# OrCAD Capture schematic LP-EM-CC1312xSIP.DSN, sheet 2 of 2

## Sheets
2 2_Mech: size A3
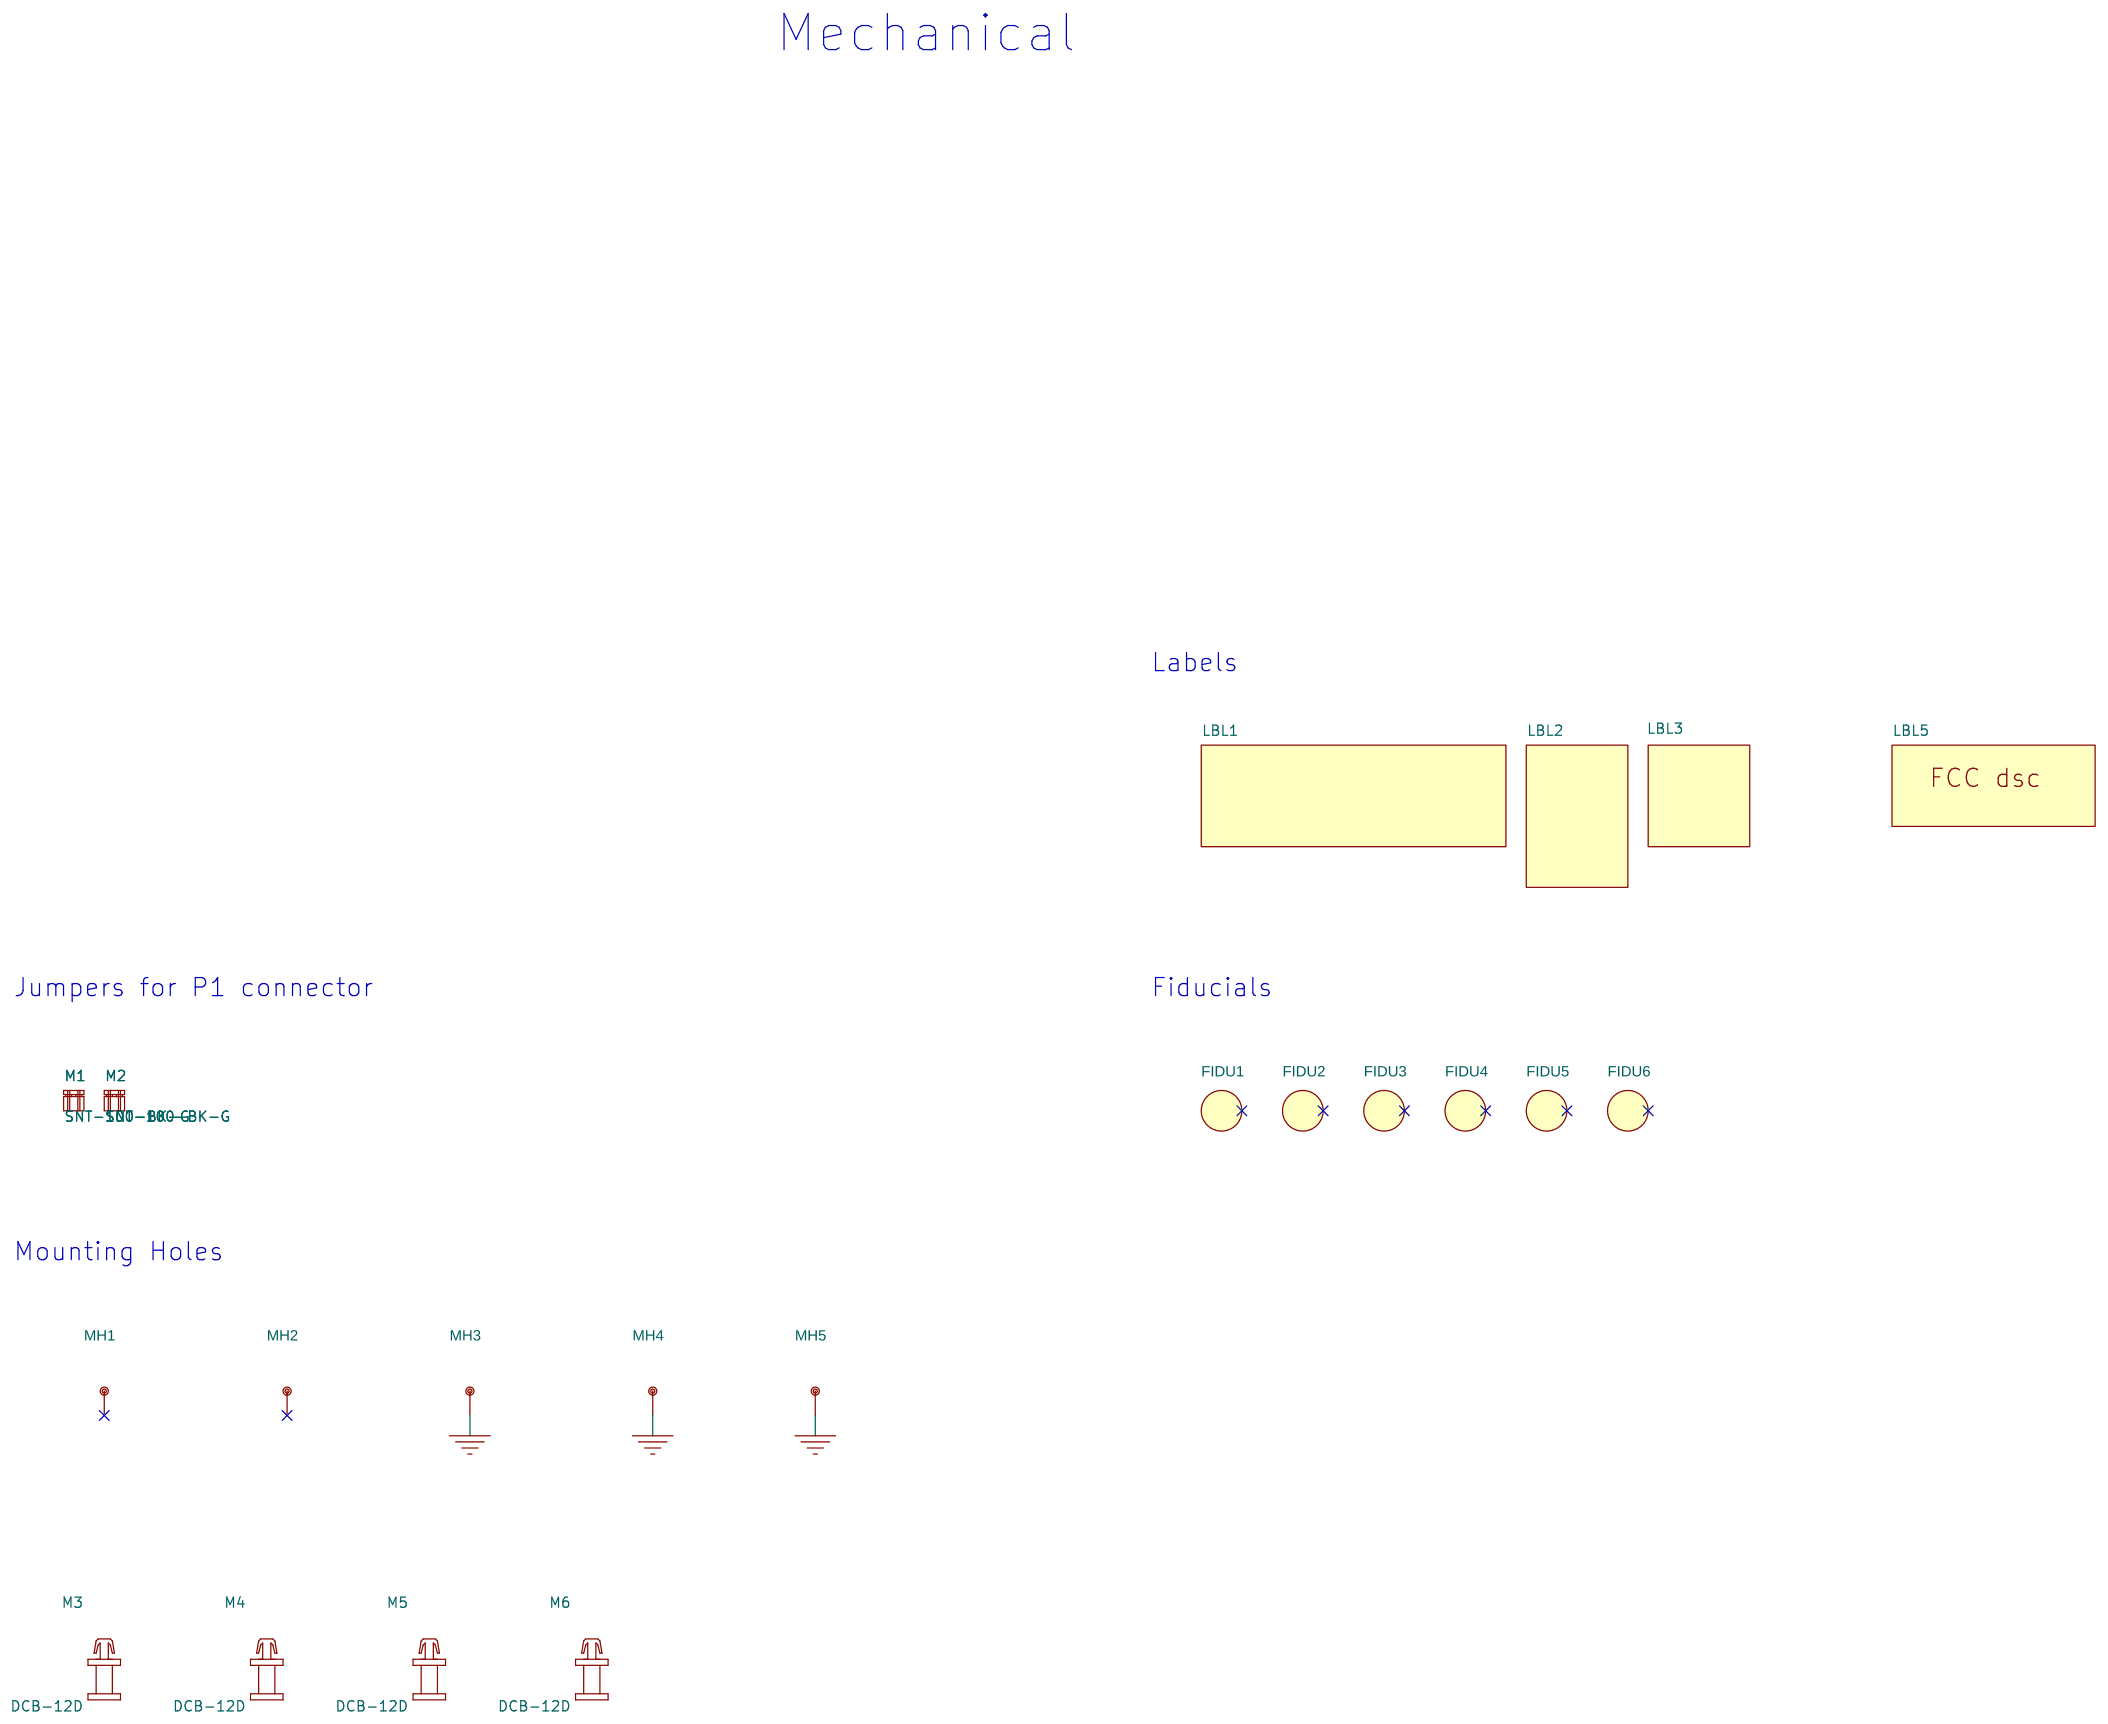
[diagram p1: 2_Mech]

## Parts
FIDU1  FIDU_1.27mm  [FID127X142]
FIDU2  FIDU_1.27mm  [FID127X142]
FIDU3  FIDU_1.27mm  [FID127X142]
FIDU4  FIDU_1.27mm  [FID127X142]
FIDU5  FIDU_1.27mm  [FID127X142]
FIDU6  FIDU_1.27mm  [FID127X142]
LBL1  TI_LOGO  [TI_LOGO_1]
LBL2  TRASH_7mm  [TRASH_7MM]
LBL3  ESD_LABEL_5x5mm  [ESD_LABEL_5X5]
LBL5  LABEL_FOR_EVALUATION_ONLY  [LABEL_FOR_EVALUATION_ONLY]
M1  SNT-100-BK-G  [SAMTEC_SNT100BKG]
M2  SNT-100-BK-G  [SAMTEC_SNT100BKG]
M3  DCB-12D  [MECH_DCB12D_A2B]
M4  DCB-12D  [MECH_DCB12D_A2B]
M5  DCB-12D  [MECH_DCB12D_A2B]
M6  DCB-12D  [MECH_DCB12D_A2B]
MH1  HOLE_3.2mm_PAD_3.8mm_PTH  [MTG320_380]
MH2  HOLE_3.2mm_PAD_3.8mm_PTH  [MTG320_380]
MH3  HOLE_3.2mm_PAD_3.8mm_PTH  [MTG320_380]
MH4  HOLE_3.2mm_PAD_3.8mm_PTH  [MTG320_380]
MH5  HOLE_1.1mm_PTH  [MTG110_170]

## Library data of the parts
FIDU1-FIDU6 = FIDMARK: NON COMPONENT, FIDUCIAL MARK, ROUND 1.27MM, SMD; Additional Datasheet URL: N/A; CLASS: IO; Country of Origin: Missing Info; Datasheet URL: N/A; Mass: N/A; Mounting Type: SMD; NOTEfied URL: https://notefied-dynamic-precision.com/NOTEfiedWebInterface/part/show?partNumber=19-00300; Packing Size: N/A; Packing Type: Missing Info; Part Number: 19-00300; Part Type: Non Component|FIDUCIAL; ROHS: Missing Info; Revision: R018; Status: Released; Texas Part Status: Under Review; Type: Non Component; Vendor: NON_COMPONENT; Vendor Part Number: FIDUCIAL_1.27mm; Vendor Part Status: Active
LBL1 = TI_LOGO_V1: NON COMPONENT, LABEL, TEXAS INSTRUMENTS LOGO; Additional Datasheet URL: N/A; AutoDoc File: https://notefied-dynamic-precision.com/DB/Apps/Desktop/Item/Object.aspx?id=87770; BU Name: TEXAS INSTRUMENTS NORWAY; Country of Origin: Missing Info; Datasheet URL: N/A; Exclusive for Customers: TEXAS INSTRUMENTS NORWAY; Mass: N/A; Mounting Type: NOT APPLY; NOTEfied URL: https://notefied-dynamic-precision.com/NOTEfiedWebInterface/part/show?partNumber=19-00350; Notes: Custom Item; Packing Size: N/A; Packing Type: Missing Info; Part Number: 19-00350; Part Type: Non Component|LABEL; ROHS: Missing Info; Revision: R020; Status: Released; Texas Part Status: Under Review; Type: Non Component; Vendor: NON_COMPONENT; Vendor Part Status: Active
LBL2 = TRASH_V2: NON COMPONENT, LABEL, TRASH 7mm; Additional Datasheet URL: N/A; Country of Origin: Missing Info; Datasheet URL: N/A; Mass: N/A; Mounting Type: NOT APPLY; NOTEfied URL: https://notefied-dynamic-precision.com/NOTEfiedWebInterface/part/show?partNumber=19-01044; Packing Size: N/A; Packing Type: Missing Info; Part Number: 19-01044; Part Type: Non Component|LABEL; ROHS: Missing Info; Revision: R014; Status: Released; Texas Part Status: Under Review; Type: Non Component; Vendor: NON_COMPONENT; Vendor Part Status: Active
LBL3 = ESD_LABEL: NON COMPONENT, LABEL, ESD, 5 X 5 mm; Additional Datasheet URL: N/A; Country of Origin: Missing Info; Datasheet URL: N/A; Mass: N/A; Maximum Operating Temperature: N/A; Minimum Operating Temperature: N/A; Mounting Type: NOT APPLY; NOTEfied URL: https://notefied-dynamic-precision.com/NOTEfiedWebInterface/part/show?partNumber=19-00471; Packing Size: N/A; Packing Type: Missing Info; Part Number: 19-00471; Part Type: Non Component|LABEL; ROHS: Not Applicable; Revision: R009; Status: Released; Type: Non Component; Vendor: NON_COMPONENT; Vendor Part Status: Active
LBL5 = LABEL_FOR_EVALUATOIN_ONLY: NON COMPONENT, LABEL, FOR EVALUATION ONLY, NOT FCC APPROVED FOR RESALE; Additional Datasheet URL: N/A; AutoDoc File: https://notefied-dynamic-precision.com/DB/Apps/Desktop/Item/Object.aspx?id=115268; BU Name: TEXAS INSTRUMENTS NORWAY; Datasheet URL: N/A; Exclusive for Customers: TEXAS INSTRUMENTS NORWAY; Mass: N/A; Maximum Operating Temperature: N/A; Minimum Operating Temperature: N/A; Mounting Type: NOT APPLY; NOTEfied URL: https://notefied-dynamic-precision.com/NOTEfiedWebInterface/part/show?partNumber=19-00830; Notes: Custom Item; Packing Size: N/A; Packing Type: Missing Info; Part Number: 19-00830; Part Type: Non Component|LABEL; REACH/SVHC Compliance: Missing Info; REACH/SVHC Details: N/A; REACH/SVHC Source: N/A; REACH/SVHC Status: Missing Info; ROHS: Missing Info; Revision: R020; Status: Released; Texas Part Status: Under Review; Type: Non Component; Vendor: NON_COMPONENT; Vendor Part Status: Active
M1 M2 = MECH_SHUNT_JUMPER_V1: MECHANIC, SHUNT, CURRENT RATING 4.3A PER PIN, 2.54 X 5.08 X 6.1mm, BLACK; Additional Datasheet URL: https://suddendocs.samtec.com/prints/snt-100-xx-x-x-mkt.pdf; AutoDoc File: https://notefied-dynamic-precision.com/DB/Apps/Desktop/Item/Object.aspx?id=104092; BU Name: DYNAMIC PRECISION GDANSK; Budget Currency: USD; Budget Price: 0.146; Budgetary Price: 0.14525 USD; Client Status: UNDER_REVIEW; Country of Origin: China,Costa Rica,Malaysia,Singapore,Taiwan,United States,Vietnam; Datasheet URL: https://suddendocs.samtec.com/catalog_english/snt.pdf; Datasheet URL 1: http://suddendocs.samtec.com/catalog_english/snt.pdf; Datasheet URL 2: http://suddendocs.samtec.com/prints/snt-100-xx-x-x-mkt.pdf; Mass: 0.11724g; Max Oper Temp: +125DEGC; Maximum Operating Temperature: +125DEGC; Min Oper Temp: -55DEGC; Minimum Operating Temperature: -55DEGC; Mounting Type: NOT APPLY; NOTEfied URL: https://notefied-dynamic-precision.com/NOTEfiedWebInterface/part/show?partNumber=19-00498; Packing Size: 1; Packing Type: Bulk; Part Number: 19-00498; Part Type: Mechanic|SHUNT; REACH/SVHC Compliance: Compliant; REACH/SVHC Details: SVHC List Version Dec 17, 2015; REACH/SVHC Source: Material Declaration; REACH/SVHC Status: Unaffected; REACH/SVHC_COMPLIANCE: COMPLIANT; REACH/SVHC_DETAILS: SVHC LIST VERSION Dec 17, 2015; REACH/SVHC_SOURCE: MATERIAL DECLARATION; REACH/SVHC_STATUS: UNAFFECTED; ROHS: Compliant; Rated Current: 4.3A; Revision: R024; RoHS Status: ROHS_COMPLIANT; Rtd Current: 4.3A; Status: Released; Texas Part Status: Under Review; Type: Mechanic; Vendor: SAMTEC; Vendor Part Status: Active; Weight: 0.11724g
M3-M6 = MECH_SPACERS_SUPPORT_V1: MECHANIC, ACCESSORY, SPACER SUPPORT, PCB DIA. 3mm, NYLON 66, NPTH; Additional Datasheet URL: https://www.kangyang-europe.com/product/pc-board-hardware/dcb-12d/; Country of Origin: Missing Info; Datasheet URL: https://www.kangyang-europe.com/wp-content/uploads/2020/02/DCB-HD.pdf; Maximum Operating Temperature: N/A; Minimum Operating Temperature: N/A; Mounting Type: NPTH; NOTEfied URL: https://notefied-dynamic-precision.com/NOTEfiedWebInterface/part/show?partNumber=13-07898; Notes: Custom libraries; Packing Size: 1000; Packing Type: Missing Info; Part Number: 13-07898; Part Type: Mechanic|ACCESSORY; REACH/SVHC Compliance: Missing Info; REACH/SVHC Source: N/A; REACH/SVHC Status: Missing Info; ROHS: Compliant; Revision: R005; Status: Released; Texas Part Status: Under Review; Type: Mechanic; Vendor: SUZHOU SOLY ELECTRICIAN; Vendor Part Status: Active
MH1-MH4 = HOLE_PTH: NON COMPONENT, HOLE 3.2mm, PLATED, PAD SIZE 3.8mm; Additional Datasheet URL: N/A; Country of Origin: Missing Info; Datasheet URL: N/A; Mass: N/A; Mounting Type: NOT APPLY; NOTEfied URL: https://notefied-dynamic-precision.com/NOTEfiedWebInterface/part/show?partNumber=19-00083; Packing Size: N/A; Packing Type: Missing Info; Part Number: 19-00083; Part Type: Non Component|HOLE|PLATED; ROHS: Missing Info; Revision: R020; Status: Released; Type: Non Component; Vendor: NON_COMPONENT; Vendor Part Status: Active
MH5 = HOLE_PTH: NON COMPONENT, HOLE 1.1mm, PLATED, PAD SIZE 1.7mm; Additional Datasheet URL: N/A; Country of Origin: Missing Info; Datasheet URL: N/A; Mass: N/A; Mounting Type: NOT APPLY; NOTEfied URL: https://notefied-dynamic-precision.com/NOTEfiedWebInterface/part/show?partNumber=19-00062; Packing Size: N/A; Packing Type: Missing Info; Part Number: 19-00062; Part Type: Non Component|HOLE|PLATED; ROHS: Missing Info; Revision: R007; Status: Released; Type: Non Component; Vendor: NON_COMPONENT; Vendor Part Number: HOLE_1.1mm_PLATED; Vendor Part Status: Active

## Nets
GND: MH3.1 MH4.1 MH5.1 ; also on sheet 1

Not connected (* = marked no-connect by the designer): FIDU1 1*; FIDU2 1*; FIDU3 1*; FIDU4 1*; FIDU5 1*; FIDU6 1*; MH1 1*; MH2 1*

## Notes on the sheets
sheet 2
- Mechanical
- Labels
- Jumpers for P1 connector
- Fiducials
- Mounting Holes
